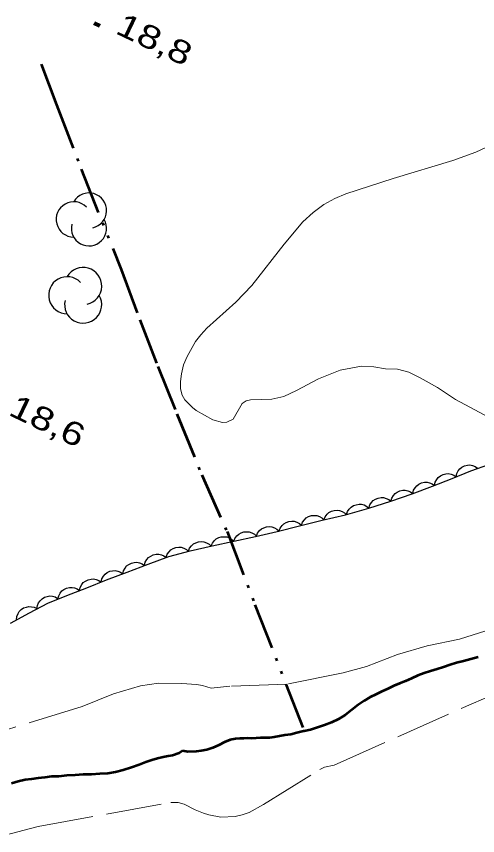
# Model space of a CAD drawing. Extents: x 355726 to 357533, y 5103782 to 5105258.
# Drawn here: x 356416.6 to 356446.5, y 5104875.3 to 5104928.3 of the extents above; entities that cross this region are included whole.
import ezdxf

# ---------------------------------------------------------------- set-up
doc = ezdxf.new("R2010")
doc.units = 0
doc.header["$LTSCALE"] = 0.6
for name, pattern in [('DASH_DOUBLE_DOT', [9.2, 5, -1.2, 0.3, -1.2, 0.3, -1.2]), ('DOT_DASHED', [7.7, 5, -1.2, 0.3, -1.2]), ('LONG_DASHED', [7.5, 6, -1.5])]:
    doc.linetypes.add(name, pattern=pattern)
for name, color, linetype, lineweight in [('2', 7, 'LONG_DASHED', 13), ('3', 7, 'Continuous', 140), ('4', 7, 'DASH_DOUBLE_DOT', 53), ('44', 7, 'Continuous', 25)]:
    doc.layers.add(name, color=color, linetype=linetype, lineweight=lineweight)

msp = doc.modelspace()

# ---------------------------------------------------------------- linework, layer by layer
at = {"layer": '2', "linetype": 'Continuous'}
msp.add_lwpolyline([(356452.24, 5104899.72), (356445.06, 5104903.55), (356443.89, 5104904.34), (356442.76, 5104904.95), (356442.04, 5104905.32), (356441.31, 5104905.51), (356440.52, 5104905.54), (356439.77, 5104905.67), (356438.98, 5104905.72), (356437.6, 5104905.46), (356436.18, 5104904.9), (356434.77, 5104904.13), (356433.94, 5104903.76), (356433.18, 5104903.57), (356431.79, 5104903.53), (356431.5, 5104903.46), (356431.24, 5104903.29), (356430.66, 5104902.28), (356430.25, 5104902.09), (356429.97, 5104902.07), (356429.36, 5104902.24), (356428.27, 5104902.84), (356428.04, 5104903.04), (356427.55, 5104903.54), (356427.37, 5104903.84), (356427.26, 5104904.24), (356427.26, 5104904.71), (356427.32, 5104905.22), (356427.46, 5104905.79), (356427.7, 5104906.33), (356428.24, 5104907.3), (356428.57, 5104907.74), (356428.97, 5104908.16), (356430.85, 5104909.86), (356431.88, 5104910.94), (356433.97, 5104913.61), (356435.18, 5104915.04), (356435.84, 5104915.66), (356436.54, 5104916.18), (356437.25, 5104916.57), (356437.96, 5104916.86), (356441.03, 5104917.86), (356444.88, 5104919.01), (356446.38, 5104919.55), (356447.07, 5104919.87)], dxfattribs=at)
at = {"layer": '2'}
for points in [[(356447.42, 5104888.72), (356445.31, 5104888.05), (356443.21, 5104887.62), (356441.31, 5104887.05), (356439.3, 5104886.29), (356437.78, 5104885.88), (356434.15, 5104885.13), (356430.46, 5104885.01), (356429.25, 5104884.87), (356428.68, 5104885.05), (356428.29, 5104885.12), (356427.35, 5104885.19), (356425.83, 5104885.21), (356424.67, 5104885.04), (356422.92, 5104884.51), (356420.9, 5104883.69), (356415.5, 5104882.04)], [(356415.82, 5104875.34), (356418.04, 5104875.93), (356426.64, 5104877.48), (356427.11, 5104877.48), (356427.5, 5104877.38), (356428.2, 5104877.01), (356428.75, 5104876.79), (356429.09, 5104876.68), (356429.86, 5104876.54), (356430.79, 5104876.58), (356431.25, 5104876.69), (356431.71, 5104876.84), (356432.63, 5104877.36), (356436.27, 5104879.62), (356436.58, 5104879.76), (356437.2, 5104879.9), (356447.51, 5104884.48)]]:
    msp.add_lwpolyline(points, dxfattribs=at)
at = {"layer": '3'}
msp.add_line((356421.68, 5104927.91), (356422.04, 5104927.74), dxfattribs=at)
at = {"layer": '4'}
for points in [[(356418.24, 5104925.25), (356419.23, 5104922.62), (356420.83, 5104918.45), (356423.41, 5104911.97), (356424.63, 5104908.71), (356425.8, 5104905.69), (356427.03, 5104902.62), (356428.63, 5104898.68), (356430.27, 5104895.01), (356432.08, 5104890.28), (356435.27, 5104882.1)], [(356446.52, 5104886.88), (356446.04, 5104886.75), (356445.57, 5104886.62), (356445.12, 5104886.51), (356444.7, 5104886.38), (356444.28, 5104886.24), (356443.87, 5104886.11), (356443.44, 5104885.98), (356443.02, 5104885.84), (356442.62, 5104885.7), (356442.21, 5104885.51), (356441.82, 5104885.33), (356441.44, 5104885.19), (356441.06, 5104885.03), (356440.68, 5104884.84), (356440.29, 5104884.67), (356439.9, 5104884.48), (356439.53, 5104884.29), (356439.15, 5104884.05)], [(356439.15, 5104884.05), (356438.76, 5104883.8), (356438.35, 5104883.48), (356437.93, 5104883.16), (356437.49, 5104882.88), (356437.04, 5104882.66), (356436.58, 5104882.48), (356436.12, 5104882.33), (356435.67, 5104882.19), (356435.27, 5104882.1), (356435.22, 5104882.09), (356434.78, 5104881.99), (356434.39, 5104881.88), (356434.01, 5104881.84), (356433.66, 5104881.78), (356433.33, 5104881.72), (356433.02, 5104881.67), (356432.73, 5104881.66), (356432.44, 5104881.66), (356432.16, 5104881.65), (356431.88, 5104881.63), (356431.62, 5104881.65), (356431.36, 5104881.63), (356431.1, 5104881.63), (356430.82, 5104881.61), (356430.47, 5104881.53), (356430.11, 5104881.38), (356429.73, 5104881.2), (356429.35, 5104881.03), (356428.97, 5104880.88), (356428.6, 5104880.82), (356428.27, 5104880.78), (356427.74, 5104880.76), (356427.38, 5104880.82), (356427.17, 5104880.67), (356426.75, 5104880.53), (356426.46, 5104880.49), (356426.13, 5104880.41), (356425.78, 5104880.33), (356425.4, 5104880.23), (356425.02, 5104880.09), (356424.58, 5104879.91), (356424.09, 5104879.74), (356423.56, 5104879.58), (356423.06, 5104879.45), (356422.56, 5104879.36), (356422.04, 5104879.33), (356421.5, 5104879.3), (356420.97, 5104879.29), (356420.45, 5104879.26), (356419.91, 5104879.23), (356419.39, 5104879.17), (356418.91, 5104879.16), (356418.48, 5104879.09), (356418.06, 5104879.05), (356417.62, 5104879), (356417.2, 5104878.94), (356416.76, 5104878.84), (356416.32, 5104878.71)]]:
    msp.add_lwpolyline(points, dxfattribs=at)
at = {"layer": '44', "linetype": 'DOT_DASHED'}
msp.add_lwpolyline([(356416.25, 5104889.08), (356417.48, 5104889.76), (356418.68, 5104890.37), (356419.91, 5104890.88), (356421.2, 5104891.38), (356422.48, 5104891.88), (356423.8, 5104892.38), (356425.16, 5104892.91), (356426.51, 5104893.4), (356427.88, 5104893.76), (356429.31, 5104894.09), (356430.72, 5104894.38), (356432.11, 5104894.7), (356433.52, 5104895.01), (356434.95, 5104895.38), (356436.43, 5104895.75), (356437.94, 5104896.09), (356439.45, 5104896.53), (356440.88, 5104896.97), (356442.25, 5104897.46), (356443.56, 5104897.94), (356444.83, 5104898.45), (356446.04, 5104898.94), (356447.28, 5104899.38)], dxfattribs=at)
at = {"layer": '44'}
for points in [[(356445.09, 5104898.56), (356445.13, 5104898.76), (356445.23, 5104898.94), (356445.33, 5104899.07), (356445.47, 5104899.18), (356445.64, 5104899.26), (356445.82, 5104899.3), (356445.98, 5104899.32), (356446.16, 5104899.28), (356446.33, 5104899.22), (356446.48, 5104899.12)], [(356443.7, 5104898), (356443.74, 5104898.2), (356443.84, 5104898.38), (356443.94, 5104898.51), (356444.08, 5104898.61), (356444.25, 5104898.7), (356444.43, 5104898.74), (356444.59, 5104898.76), (356444.77, 5104898.72), (356444.94, 5104898.65), (356445.09, 5104898.55)], [(356442.29, 5104897.48), (356442.34, 5104897.68), (356442.45, 5104897.85), (356442.55, 5104897.98), (356442.69, 5104898.08), (356442.86, 5104898.16), (356443.05, 5104898.2), (356443.21, 5104898.21), (356443.38, 5104898.17), (356443.55, 5104898.1), (356443.7, 5104897.99)], [(356440.88, 5104896.97), (356440.93, 5104897.17), (356441.04, 5104897.35), (356441.14, 5104897.47), (356441.29, 5104897.57), (356441.45, 5104897.65), (356441.64, 5104897.68), (356441.8, 5104897.7), (356441.98, 5104897.65), (356442.15, 5104897.58), (356442.29, 5104897.47)], [(356439.45, 5104896.53), (356439.51, 5104896.73), (356439.62, 5104896.9), (356439.73, 5104897.02), (356439.88, 5104897.11), (356440.05, 5104897.18), (356440.24, 5104897.21), (356440.4, 5104897.21), (356440.57, 5104897.16), (356440.74, 5104897.08), (356440.88, 5104896.97)], [(356438, 5104896.11), (356438.07, 5104896.31), (356438.18, 5104896.47), (356438.3, 5104896.6), (356438.45, 5104896.69), (356438.62, 5104896.75), (356438.81, 5104896.78), (356438.97, 5104896.78), (356439.14, 5104896.73), (356439.31, 5104896.64), (356439.45, 5104896.53)], [(356435.09, 5104895.41), (356435.16, 5104895.61), (356435.28, 5104895.77), (356435.4, 5104895.89), (356435.55, 5104895.98), (356435.73, 5104896.04), (356435.92, 5104896.05), (356436.08, 5104896.05), (356436.25, 5104895.99), (356436.41, 5104895.9), (356436.54, 5104895.78)], [(356436.54, 5104895.78), (356436.62, 5104895.97), (356436.74, 5104896.13), (356436.86, 5104896.24), (356437.02, 5104896.33), (356437.2, 5104896.38), (356437.39, 5104896.39), (356437.55, 5104896.38), (356437.71, 5104896.32), (356437.87, 5104896.23), (356438.01, 5104896.1)], [(356433.63, 5104895.04), (356433.7, 5104895.24), (356433.83, 5104895.4), (356433.94, 5104895.52), (356434.09, 5104895.6), (356434.27, 5104895.67), (356434.46, 5104895.68), (356434.62, 5104895.68), (356434.79, 5104895.62), (356434.95, 5104895.53), (356435.09, 5104895.42)], [(356430.71, 5104894.38), (356430.78, 5104894.57), (356430.91, 5104894.73), (356431.03, 5104894.85), (356431.18, 5104894.93), (356431.36, 5104894.99), (356431.55, 5104895), (356431.71, 5104894.99), (356431.88, 5104894.93), (356432.04, 5104894.84), (356432.17, 5104894.71)], [(356432.17, 5104894.71), (356432.25, 5104894.91), (356432.37, 5104895.07), (356432.49, 5104895.18), (356432.65, 5104895.26), (356432.83, 5104895.32), (356433.02, 5104895.33), (356433.18, 5104895.32), (356433.34, 5104895.25), (356433.5, 5104895.16), (356433.64, 5104895.04)], [(356427.78, 5104893.74), (356427.85, 5104893.93), (356427.98, 5104894.09), (356428.1, 5104894.21), (356428.25, 5104894.29), (356428.43, 5104894.35), (356428.62, 5104894.36), (356428.78, 5104894.35), (356428.95, 5104894.29), (356429.11, 5104894.2), (356429.24, 5104894.07)], [(356429.24, 5104894.08), (356429.32, 5104894.27), (356429.45, 5104894.43), (356429.57, 5104894.54), (356429.73, 5104894.62), (356429.9, 5104894.67), (356430.09, 5104894.68), (356430.26, 5104894.66), (356430.42, 5104894.6), (356430.58, 5104894.5), (356430.71, 5104894.38)], [(356426.33, 5104893.35), (356426.4, 5104893.55), (356426.52, 5104893.71), (356426.63, 5104893.83), (356426.78, 5104893.92), (356426.96, 5104893.98), (356427.15, 5104894), (356427.31, 5104894), (356427.48, 5104893.94), (356427.64, 5104893.85), (356427.78, 5104893.73)], [(356424.92, 5104892.82), (356424.97, 5104893.03), (356425.08, 5104893.2), (356425.18, 5104893.33), (356425.33, 5104893.43), (356425.49, 5104893.51), (356425.68, 5104893.54), (356425.85, 5104893.55), (356426.02, 5104893.51), (356426.19, 5104893.44), (356426.33, 5104893.34)], [(356423.53, 5104892.27), (356423.57, 5104892.48), (356423.67, 5104892.65), (356423.77, 5104892.79), (356423.92, 5104892.89), (356424.08, 5104892.97), (356424.27, 5104893.01), (356424.43, 5104893.03), (356424.6, 5104892.99), (356424.78, 5104892.92), (356424.93, 5104892.82)], [(356422.12, 5104891.75), (356422.17, 5104891.95), (356422.27, 5104892.12), (356422.38, 5104892.25), (356422.52, 5104892.36), (356422.69, 5104892.44), (356422.87, 5104892.47), (356423.04, 5104892.49), (356423.21, 5104892.45), (356423.38, 5104892.38), (356423.53, 5104892.28)], [(356420.73, 5104891.2), (356420.77, 5104891.4), (356420.87, 5104891.58), (356420.97, 5104891.71), (356421.12, 5104891.81), (356421.28, 5104891.89), (356421.47, 5104891.93), (356421.63, 5104891.95), (356421.8, 5104891.91), (356421.98, 5104891.84), (356422.13, 5104891.74)], [(356419.33, 5104890.65), (356419.38, 5104890.86), (356419.48, 5104891.03), (356419.58, 5104891.17), (356419.72, 5104891.27), (356419.88, 5104891.35), (356420.07, 5104891.39), (356420.24, 5104891.4), (356420.41, 5104891.37), (356420.58, 5104891.3), (356420.73, 5104891.2)], [(356417.97, 5104890.01), (356418, 5104890.22), (356418.08, 5104890.4), (356418.17, 5104890.54), (356418.3, 5104890.66), (356418.46, 5104890.76), (356418.64, 5104890.82), (356418.8, 5104890.85), (356418.98, 5104890.83), (356419.15, 5104890.78), (356419.31, 5104890.69)], [(356416.65, 5104889.3), (356416.67, 5104889.51), (356416.75, 5104889.7), (356416.83, 5104889.84), (356416.96, 5104889.96), (356417.11, 5104890.07), (356417.29, 5104890.13), (356417.45, 5104890.17), (356417.62, 5104890.15), (356417.8, 5104890.11), (356417.97, 5104890.03)]]:
    msp.add_lwpolyline(points, dxfattribs=at)
for centre, radius, start, end in [((356421.337, 5104915.777), 1.142, 282.2692, 149.7263), ((356420.355, 5104915.206), 1.142, 44.1154, 269.804), ((356421.337, 5104914.635), 1.142, 166.9369, 29.6212), ((356420.962, 5104910.898), 1.202, 282.2692, 149.7263), ((356419.928, 5104910.297), 1.202, 44.1154, 269.804), ((356420.962, 5104909.696), 1.202, 166.9369, 29.6212)]:
    msp.add_arc(centre, radius, start, end, dxfattribs=at)

# ---------------------------------------------------------------- texts
at = {"layer": '3', "width": 1.3}
for s, p in [('18,8   ', (356422.97, 5104927.28)), ('18,6   ', (356416.05, 5104902.59))]:
    msp.add_text(s, height=1.5, rotation=334.423, dxfattribs=at).set_placement(p)

doc.saveas('drawing.dxf')
